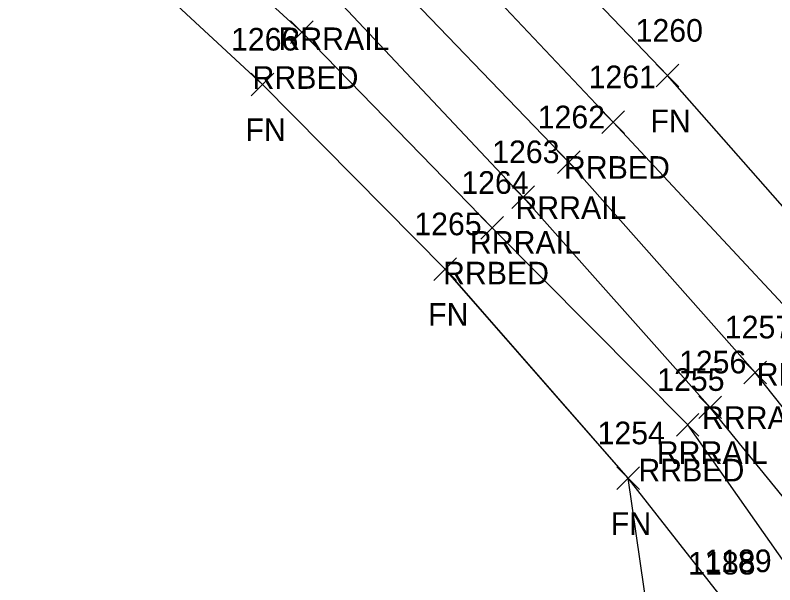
# Model space of a CAD drawing. Extents: x 1715662 to 1717487, y 887396 to 890004.
# Drawn here: x 1716283.7 to 1716350.8, y 888349 to 888399.3 of the extents above; entities that cross this region are included whole.
import ezdxf

# ---------------------------------------------------------------- set-up
doc = ezdxf.new("R2010")
doc.units = 0
for name, color, linetype in [('L_A', 7, 'Continuous'), ('L_I', 7, 'Continuous'), ('L_TIC', 7, 'Continuous'), ('LFNC', 7, 'Continuous'), ('LSOGP', 7, 'Continuous'), ('R_A', 7, 'Continuous'), ('R_I', 7, 'Continuous'), ('R_TIC', 7, 'Continuous'), ('RR', 7, 'Continuous'), ('RRB', 7, 'Continuous')]:
    doc.layers.add(name, color=color, linetype=linetype)

msp = doc.modelspace()

# ---------------------------------------------------------------- linework, layer by layer
at = {"layer": 'L_TIC'}
for points in [[(1716340.376, 888393.001), (1716342.376, 888395.001)], [(1716342.376, 888393.001), (1716340.376, 888395.001)], [(1716304.606, 888392.218), (1716306.606, 888394.218)], [(1716306.606, 888392.218), (1716304.606, 888394.218)], [(1716320.742, 888375.902), (1716322.742, 888377.902)], [(1716322.742, 888375.902), (1716320.742, 888377.902)], [(1716336.883, 888357.435), (1716338.883, 888359.435)], [(1716338.883, 888357.435), (1716336.883, 888359.435)]]:
    msp.add_lwpolyline(points, dxfattribs=at)
at = {"layer": 'LFNC'}
for points in [[(1716443.098, 888280.317), (1716420.433, 888282.989), (1716412.543, 888296.715), (1716401.348, 888315.282), (1716386.51, 888337.853), (1716374.785, 888353.899), (1716358.025, 888375.078), (1716341.376, 888394.001), (1716322.754, 888413.454), (1716303.71, 888431.095), (1716282.224, 888449.189), (1716263.808, 888463.099), (1716243.953, 888476.997), (1716231.603, 888485.189), (1716232.765, 888492.604)], [(1716393.469, 888277.838), (1716385.773, 888290.591), (1716373.292, 888310.5), (1716357.546, 888332.847), (1716346.753, 888347.139), (1716337.883, 888358.435), (1716321.742, 888376.902), (1716305.606, 888393.218), (1716286.544, 888410.885), (1716268.192, 888426.034), (1716248.019, 888441.452), (1716229.393, 888453.959), (1716214.648, 888463.044)]]:
    msp.add_lwpolyline(points, dxfattribs=at)
at = {"layer": 'LSOGP'}
for points in [[(1716469.007, 888433.308), (1716446.639, 888397.104), (1716439.784, 888394.85), (1716438.641, 888388.155), (1716443.71, 888383.152), (1716446.38, 888343.601), (1716442.786, 888319.775), (1716434.149, 888303.757), (1716410.201, 888303.478), (1716401.342, 888315.278), (1716398.071, 888328.134), (1716386.509, 888337.85), (1716374.78, 888353.896), (1716358.023, 888375.075), (1716341.376, 888394), (1716322.749, 888413.449)], [(1716286.539, 888410.877), (1716305.604, 888393.215), (1716321.739, 888376.899), (1716337.876, 888358.43), (1716340.326, 888341.329), (1716339.086, 888339.817), (1716334.375, 888337.45), (1716332.654, 888333.371), (1716332.506, 888333.427), (1716309.755, 888326.671), (1716279.78, 888323.124)]]:
    msp.add_lwpolyline(points, dxfattribs=at)
at = {"layer": 'R_TIC'}
for points in [[(1716308.064, 888396.835), (1716310.064, 888398.835)], [(1716310.064, 888396.835), (1716308.064, 888398.835)], [(1716335.573, 888388.892), (1716337.573, 888390.892)], [(1716337.573, 888388.892), (1716335.573, 888390.892)], [(1716331.642, 888385.349), (1716333.642, 888387.349)], [(1716333.642, 888385.349), (1716331.642, 888387.349)], [(1716327.621, 888382.271), (1716329.621, 888384.271)], [(1716329.621, 888382.271), (1716327.621, 888384.271)], [(1716324.893, 888379.56), (1716326.893, 888381.56)], [(1716326.893, 888379.56), (1716324.893, 888381.56)], [(1716348.123, 888366.789), (1716350.123, 888368.789)], [(1716350.123, 888366.789), (1716348.123, 888368.789)], [(1716344.129, 888363.699), (1716346.129, 888365.699)], [(1716346.129, 888363.699), (1716344.129, 888365.699)], [(1716342.151, 888362.152), (1716344.151, 888364.152)], [(1716344.151, 888362.152), (1716342.151, 888364.152)]]:
    msp.add_lwpolyline(points, dxfattribs=at)
at = {"layer": 'RR'}
for points in [[(1716436.006, 888215.337), (1716430.823, 888230.215), (1716426.348, 888241.635), (1716416.677, 888263.628), (1716410.086, 888277.215), (1716402.001, 888292.439), (1716390.919, 888310.944), (1716376.876, 888331.991), (1716364.819, 888348.018), (1716349.123, 888367.789), (1716332.642, 888386.349), (1716315.07, 888404.654), (1716296.205, 888422.302), (1716278.069, 888437.86), (1716256.9, 888454.27), (1716238.515, 888467.25), (1716223.556, 888476.476), (1716202.573, 888488.846), (1716178.442, 888501.208), (1716153.561, 888512.412), (1716127.616, 888522.226), (1716099.939, 888531.037), (1716073.491, 888537.688), (1716046.147, 888542.834)], [(1716430.72, 888215.397), (1716425.304, 888230.283), (1716421.076, 888241.431), (1716411.445, 888263.23), (1716405.098, 888275.915), (1716397.082, 888291.053), (1716387.606, 888308.839), (1716372.559, 888329.716), (1716360.984, 888345.241), (1716345.129, 888364.699), (1716328.621, 888383.271), (1716311.711, 888401.255), (1716292.491, 888418.83), (1716274.069, 888433.953), (1716254.21, 888450.025), (1716235.796, 888462.901), (1716221.101, 888472.304), (1716200.717, 888484.158), (1716175.893, 888496.909), (1716151.922, 888507.643), (1716125.759, 888517.559), (1716098.568, 888526.188), (1716072.377, 888532.71), (1716045.904, 888537.783)]]:
    msp.add_lwpolyline(points, dxfattribs=at)
at = {"layer": 'RRB'}
for points in [[(1716413.209, 888279.935), (1716405.549, 888293.581), (1716393.281, 888311.771), (1716381.094, 888334.374), (1716367.434, 888349.07), (1716353.599, 888371.628), (1716336.573, 888389.892), (1716318.547, 888409.005), (1716299.812, 888426.157), (1716280.583, 888443.639), (1716260.294, 888458.826), (1716240.844, 888471.367), (1716225.46, 888478.919)], [(1716402.391, 888277.055), (1716395.087, 888289.895), (1716384.284, 888307.273), (1716369.213, 888328.084), (1716357.094, 888343.322), (1716343.151, 888363.152), (1716325.893, 888380.56), (1716309.064, 888397.835), (1716289.633, 888415.582), (1716271.912, 888431.207), (1716252.081, 888447.529), (1716234.746, 888461.341), (1716219.561, 888469.487)]]:
    msp.add_lwpolyline(points, dxfattribs=at)

# ---------------------------------------------------------------- texts
at = {"layer": 'L_A'}
for p in [(1716339.856, 888389.001), (1716304.087, 888388.218), (1716320.222, 888371.902), (1716336.363, 888353.435)]:
    msp.add_text('FN', height=2, dxfattribs=at).set_placement(p)
at = {"layer": 'L_I'}
for s, p in [('1260', (1716338.549, 888397.001)), ('1266', (1716302.811, 888396.218)), ('1265', (1716319.002, 888379.902)), ('1254', (1716335.19, 888361.435)), ('1189', (1716344.619, 888350.139))]:
    msp.add_text(s, height=2, dxfattribs=at).set_placement(p)
at = {"layer": 'R_A'}
for s, p in [('RRRAIL', (1716307.002, 888396.255)), ('RRBED', (1716304.71, 888392.835)), ('RRBED', (1716332.218, 888384.892)), ('RRRAIL', (1716327.933, 888381.349)), ('RRRAIL', (1716323.912, 888378.271)), ('RRBED', (1716321.539, 888375.56)), ('RRBED', (1716349.245, 888366.628)), ('RRRAIL', (1716344.414, 888362.789)), ('RRRAIL', (1716340.421, 888359.699)), ('RRBED', (1716338.797, 888358.152))]:
    msp.add_text(s, height=2, dxfattribs=at).set_placement(p)
at = {"layer": 'R_I'}
for s, p in [('1261', (1716334.399, 888392.892)), ('1262', (1716329.902, 888389.349)), ('1263', (1716325.88, 888386.271)), ('1264', (1716323.153, 888383.56)), ('1257', (1716346.43, 888370.789)), ('1256', (1716342.381, 888367.699)), ('1255', (1716340.458, 888366.152)), ('1188', (1716343.195, 888349.931))]:
    msp.add_text(s, height=2, dxfattribs=at).set_placement(p)

doc.saveas('drawing.dxf')
